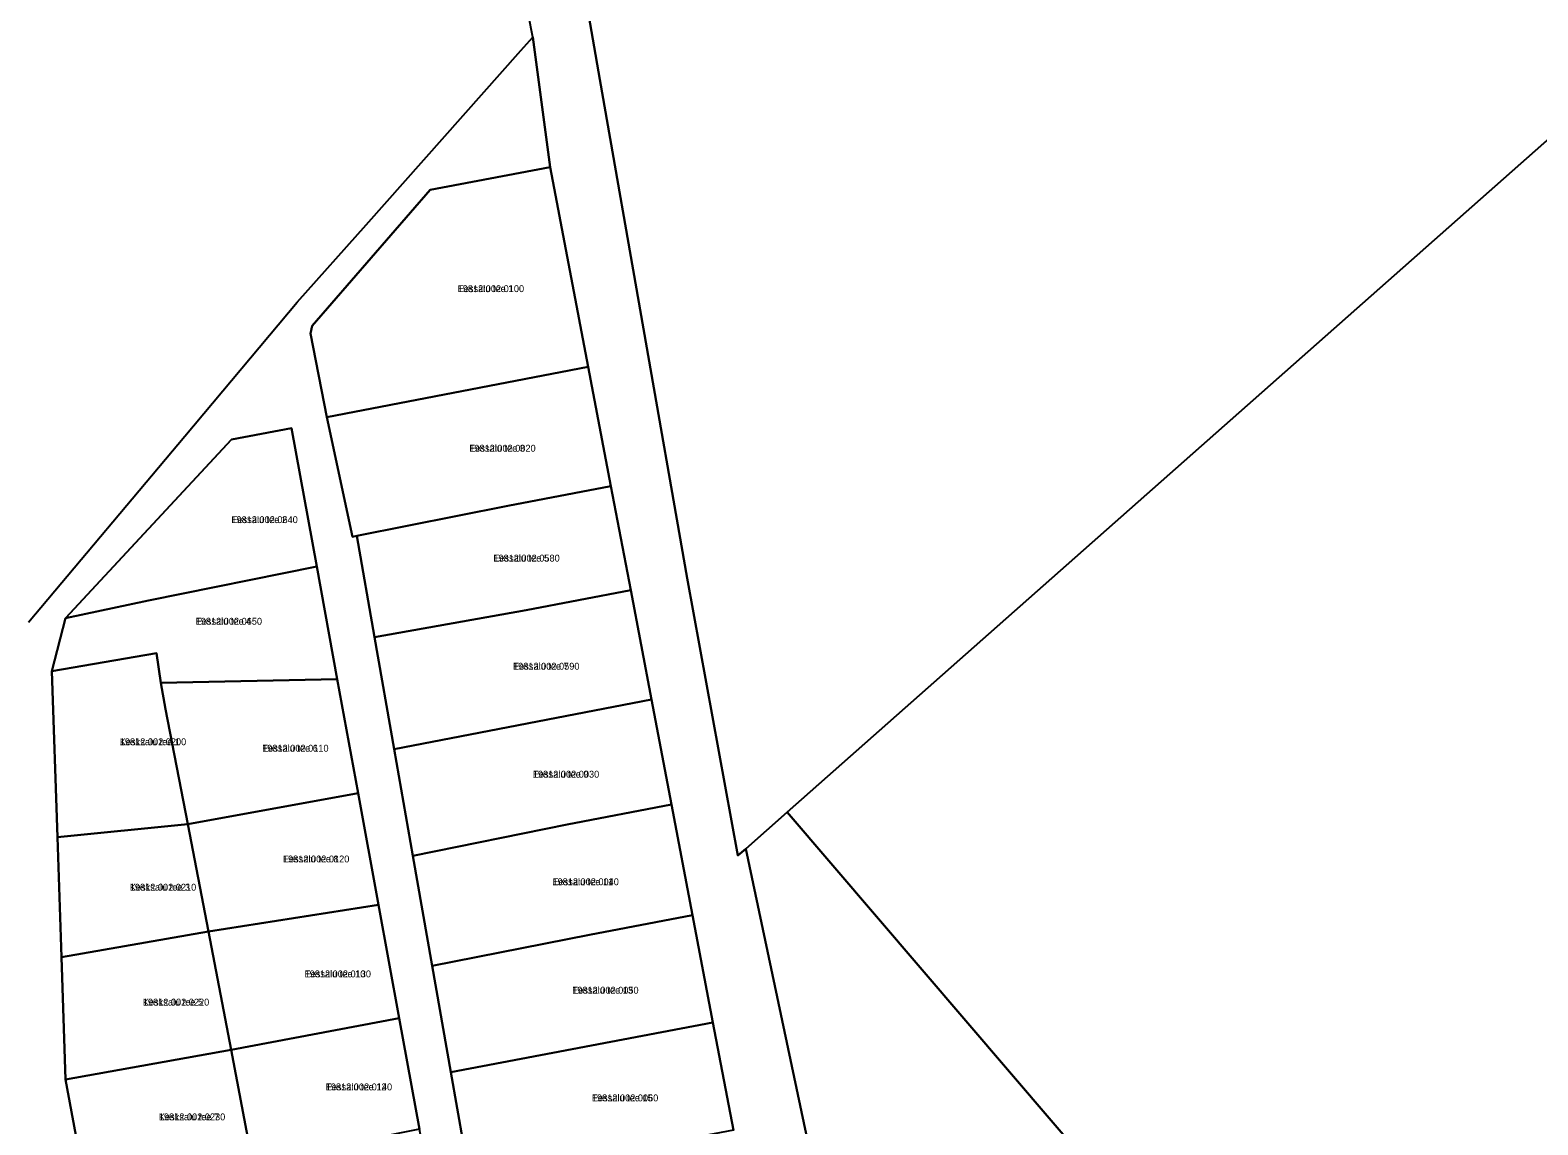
# Model space of a CAD drawing. Extents: x 516875 to 535633, y 6574491 to 6593094.
# Drawn here: x 517649.9 to 517979.1, y 6586096.9 to 6586335.9 of the extents above; entities that cross this region are included whole.
import ezdxf

# ---------------------------------------------------------------- set-up
doc = ezdxf.new("R2010")
doc.units = 0
for name, color, linetype in [('L_AADRESS', 7, 'Continuous'), ('PIIR', 7, 'Continuous'), ('TUNNUS', 7, 'Continuous')]:
    doc.layers.add(name, color=color, linetype=linetype)

msp = doc.modelspace()

# ---------------------------------------------------------------- linework, layer by layer
at = {"layer": 'PIIR'}
for points in [[(518339.07, 6586628.45), (517815.18, 6586165.19), (517806.19, 6586157.23), (517804.46, 6586155.78), (517793.35, 6586216.31), (517774.34, 6586325.17), (517766.65, 6586369.26)], [(517766.65, 6586369.26), (517774.34, 6586325.17), (517793.35, 6586216.31), (517804.46, 6586155.78), (517806.19, 6586157.23), (517834.45, 6586023.84), (517838.36, 6586028.8), (517840.48, 6586031.48), (517874.27, 6585899.13), (517867.52, 6585889.23), (517901.09, 6585752.36), (517906.97, 6585760.2), (517921.43, 6585688.63)], [(517803.47, 6586095.78), (517799, 6586119.26), (517794.54, 6586142.74), (517789.96, 6586166.85), (517785.58, 6586189.83), (517781.05, 6586213.68), (517776.73, 6586236.39), (517771.78, 6586262.46), (517763.49, 6586306.06), (517759.68, 6586334.4), (517757.79, 6586344.11)], [(517649.54, 6586206.67), (517683.68, 6586247.27), (517708.26, 6586276.58), (517723.26, 6586293.41), (517757.09, 6586331.49), (517759.68, 6586334.4), (517763.49, 6586306.06), (517737.24, 6586301.07), (517711.47, 6586271.39), (517711.14, 6586269.7), (517714.67, 6586251.44), (517720.29, 6586225.35), (517721.26, 6586225.55), (517725.13, 6586203.45), (517729.41, 6586178.96), (517733.49, 6586155.68), (517737.69, 6586131.66), (517741.75, 6586108.44), (517745.9, 6586084.9)]]:
    msp.add_lwpolyline(points, dxfattribs=at)
for points in [[(518339.07, 6586628.45), (518368.92, 6586501.61), (518469.32, 6586537.66), (518667.98, 6586124.83), (518455.99, 6585991.72), (518141.14, 6585794.01), (518029.21, 6585923.05), (517949.91, 6586010.16), (517883.26, 6586085.77), (517815.18, 6586165.19)], [(517711.14, 6586269.7), (517711.47, 6586271.39), (517737.24, 6586301.07), (517763.49, 6586306.06), (517771.78, 6586262.46), (517714.67, 6586251.44)], [(517771.78, 6586262.46), (517776.73, 6586236.39), (517754.19, 6586232.1), (517721.26, 6586225.55), (517720.29, 6586225.35), (517714.67, 6586251.44)], [(517712.48, 6586016.72), (517748.05, 6586024.53), (517743.97, 6586046.81), (517739.53, 6586071.08), (517734.97, 6586095.98), (517730.53, 6586120.24), (517726, 6586144.99), (517721.54, 6586169.36), (517716.99, 6586194.28), (517712.49, 6586218.83), (517706.96, 6586249.08), (517693.92, 6586246.57), (517657.68, 6586207.57), (517654.67, 6586195.96), (517655.87, 6586159.72), (517656.74, 6586133.57), (517657.63, 6586106.83), (517662.18, 6586082.56), (517667, 6586056.85), (517671.44, 6586033.2), (517676.21, 6586007.79)], [(517675.79, 6586211.41), (517657.68, 6586207.57), (517693.92, 6586246.57), (517706.96, 6586249.08), (517712.49, 6586218.83)], [(517721.26, 6586225.55), (517754.19, 6586232.1), (517776.73, 6586236.39), (517781.05, 6586213.68), (517758.23, 6586209.34), (517725.13, 6586203.45)], [(517677.51, 6586199.95), (517654.67, 6586195.96), (517657.68, 6586207.57), (517675.79, 6586211.41), (517712.49, 6586218.83), (517716.99, 6586194.28), (517678.49, 6586193.45)], [(517729.41, 6586178.96), (517725.13, 6586203.45), (517758.23, 6586209.34), (517781.05, 6586213.68), (517785.58, 6586189.83)], [(517654.67, 6586195.96), (517677.51, 6586199.95), (517678.49, 6586193.45), (517679.48, 6586187.69), (517684.33, 6586162.56), (517655.87, 6586159.72)], [(517721.54, 6586169.36), (517684.33, 6586162.56), (517679.48, 6586187.69), (517678.49, 6586193.45), (517716.99, 6586194.28)], [(517729.41, 6586178.96), (517785.58, 6586189.83), (517789.96, 6586166.85), (517767.21, 6586162.52), (517733.49, 6586155.68)], [(517684.33, 6586162.56), (517721.54, 6586169.36), (517726, 6586144.99), (517688.85, 6586139.13)], [(517772.02, 6586138.46), (517737.69, 6586131.66), (517733.49, 6586155.68), (517767.21, 6586162.52), (517789.96, 6586166.85), (517794.54, 6586142.74)], [(517815.18, 6586165.19), (517883.26, 6586085.77), (517838.36, 6586028.8), (517834.45, 6586023.84), (517806.19, 6586157.23)], [(517655.87, 6586159.72), (517684.33, 6586162.56), (517688.85, 6586139.13), (517656.74, 6586133.57)], [(517688.85, 6586139.13), (517726, 6586144.99), (517730.53, 6586120.24), (517693.84, 6586113.3)], [(517741.75, 6586108.44), (517737.69, 6586131.66), (517772.02, 6586138.46), (517794.54, 6586142.74), (517799, 6586119.26)], [(517656.74, 6586133.57), (517688.85, 6586139.13), (517693.84, 6586113.3), (517657.63, 6586106.83)], [(517693.84, 6586113.3), (517730.53, 6586120.24), (517734.97, 6586095.98), (517698.5, 6586088.71)], [(517741.75, 6586108.44), (517799, 6586119.26), (517803.47, 6586095.78), (517745.9, 6586084.9)], [(517662.18, 6586082.56), (517657.63, 6586106.83), (517693.84, 6586113.3), (517698.5, 6586088.71)]]:
    msp.add_lwpolyline(points, close=True, dxfattribs=at)

# ---------------------------------------------------------------- texts
at = {"layer": 'L_AADRESS'}
for s, p in [('Eessalu tee 1', (517743.27, 6586278.75)), ('Eessalu tee 3', (517745.8, 6586243.91)), ('Eessalu tee 2', (517693.86, 6586228.32)), ('Eessalu tee 5', (517751.05, 6586219.92)), ('Eessalu tee 4', (517686.06, 6586206.14)), ('Eessalu tee 7', (517755.36, 6586196.32)), ('Kesksalu tee 1', (517669.5, 6586179.82)), ('Eessalu tee 6', (517700.58, 6586178.42)), ('Eessalu tee 9', (517759.67, 6586172.75)), ('Eessalu tee 8', (517705.12, 6586154.24)), ('Eessalu tee 11', (517763.96, 6586149.26)), ('Kesksalu tee 3', (517671.69, 6586148.07)), ('Eessalu tee 10', (517709.84, 6586129.15)), ('Eessalu tee 13', (517768.27, 6586125.59)), ('Kesksalu tee 5', (517674.53, 6586122.98)), ('Eessalu tee 12', (517714.46, 6586104.48)), ('Eessalu tee 15', (517772.57, 6586102.08)), ('Kesksalu tee 7', (517678.03, 6586097.93))]:
    msp.add_text(s, height=1.5, dxfattribs=at).set_placement(p)
at = {"layer": 'TUNNUS'}
for s, p in [('19812:002:0100', (517743.27, 6586278.75)), ('19812:002:0020', (517745.8, 6586243.91)), ('19812:002:0640', (517693.86, 6586228.32)), ('19812:002:0580', (517751.05, 6586219.92)), ('19812:002:0650', (517686.06, 6586206.14)), ('19812:002:0590', (517755.36, 6586196.32)), ('19812:002:0200', (517669.5, 6586179.82)), ('19812:002:0110', (517700.58, 6586178.42)), ('19812:002:0030', (517759.67, 6586172.75)), ('19812:002:0120', (517705.12, 6586154.24)), ('19812:002:0040', (517763.96, 6586149.26)), ('19812:002:0210', (517671.69, 6586148.07)), ('19812:002:0130', (517709.84, 6586129.15)), ('19812:002:0050', (517768.27, 6586125.59)), ('19812:002:0220', (517674.53, 6586122.98)), ('19812:002:0140', (517714.46, 6586104.48)), ('19812:002:0060', (517772.57, 6586102.08)), ('19812:002:0230', (517678.03, 6586097.93))]:
    msp.add_text(s, height=1.5, dxfattribs=at).set_placement(p)

doc.saveas('drawing.dxf')
